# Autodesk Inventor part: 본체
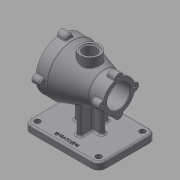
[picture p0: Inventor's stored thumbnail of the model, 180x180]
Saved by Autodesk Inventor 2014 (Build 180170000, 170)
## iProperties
Created: 2020-12
Part Number: 본체
Material: Generic
Document SubType Name: Modeling
Designer: kh
Density: 1 g/cm^3
Appearance: Default
Author: kh
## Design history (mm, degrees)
sketch "스케치1"
  geometry: L1 (-65, 50)-(65, 50); L2 (65, 50)-(65, -50); L3 (65, -50)-(-65, -50); L4 (-65, -50)-(-65, 50); L5 (-65, 50)-(65, -50); L6 (65, 50)-(-65, -50); 1 further point
  constraints: 12 end point, 2 midpoint, 2 parallel, 1 horizontal, 1 perpendicular
  dimensions: "d0" = 130 distance between parallel lines of L2 L4; "d1" = 100 distance between parallel lines of L3 L1
extrude "돌출1" new body sketch "스케치1" distance "d2" = 12; taper "d3" = 0 deg
sketch "스케치2"
  geometry: L1 (50, 82)-(-50, 82); L2 (-50, 82)-(-50, 109.5); L3 (-50, 109.5)-(-25, 109.5); L4 (-25, 109.5)-(30, 126); L5 (30, 126)-(50, 126); L6 (50, 126)-(50, 82); 2 further points
  constraints: 12 end point, 3 parallel, 1 horizontal, 1 midpoint, 1 perpendicular, 1 vertical alignment
  dimensions: "d4" = 82 distance from line of point (0, 0) L1; "d5" = 100 distance between parallel lines of L2 L6; "d6" = 55 diameter of L3 L1; "d7" = 88 diameter of L5 L1; "d8" = 20 distance of L4.end L5.end; "d119" = 25 distance of L2.end L3.end
revolve "회전1" sketch "스케치2" stored, may be unused: angle "d9" = 90 deg
sketch "스케치3"
  geometry: L1 (-24, 74.215)-(24, 74.215); L2 (24, 74.215)-(24, 0); L3 (24, 0)-(-24, 0); L4 (-24, 0)-(-24, 74.215); L5 (-24, 74.215)-(24, 0); L6 (24, 74.215)-(-24, 0); L7 (-65, 0)-(65, 0) reference; 4 further points
  constraints: 12 end point, 5 midpoint, 2 parallel, 1 horizontal, 1 perpendicular, 1 vertical alignment
  dimensions: "d10" = 48 distance between parallel lines of L2 L4
extrude "돌출2" join sketch "스케치3" stored distance "d11" = 8; taper "d12" = 0 deg
sketch "스케치4"
  geometry: L1 (-25, 75.287)-(25, 75.287); L2 (25, 75.287)-(25, 0); L3 (25, 0)-(-25, 0); L4 (-25, 0)-(-25, 75.287); L5 (-25, 75.287)-(25, 0); L6 (25, 75.287)-(-25, 0); 3 further points
  constraints: 12 end point, 4 midpoint, 2 parallel, 1 horizontal, 1 perpendicular, 1 vertical alignment
  dimensions: "d13" = 50 distance between parallel lines of L2 L4
extrude "돌출3" join sketch "스케치4" distance "d14" = 8; taper "d15" = 0 deg
sketch "스케치5"
  geometry: C1 r 7 at (0, 44); 2 further points
  constraints: 2 vertical alignment, 1 centre point, 1 other
  dimensions: "d16" = 7 radius of C1
extrude "돌출4" join sketch "스케치5" distance "d17" = 15; taper "d18" = 0 deg
hole "구멍1" diameter "d21" = 4.134; stored, may be unused: countersink angle "d25" = 90 deg, drill point angle "d27" = 118 deg; dims "d19" = 10, "d20" = 10, "d22" = 9, "d23" = 4, "d24" = 2, "d26" = 11
sketch "스케치6"
  geometry: C1 r 7 at (0, 27.5); 2 further points
  constraints: 2 vertical alignment, 1 centre point, 1 other
  dimensions: "d32" = 7 radius of C1
extrude "돌출5" join sketch "스케치6" distance "d33" = 15; taper "d34" = 0 deg
hole "구멍2" diameter "d37" = 4.134; stored, may be unused: countersink angle "d41" = 90 deg, drill point angle "d43" = 118 deg; dims "d35" = 10, "d36" = 10, "d38" = 9, "d39" = 4, "d40" = 2, "d42" = 11
node "작업 평면1"
sketch "스케치7"
  geometry: C1 r 17 at (0, 0); 1 further point
  constraints: 1 centre point, 1 coincident
  dimensions: "d48" = 34 diameter of C1
extrude "돌출6" join sketch "스케치7" distance "d49" = 32.75; taper "d50" = 0 deg
sketch "스케치8"
  geometry: L1 (50, 82)-(-50, 82); L2 (-50, 82)-(-50, 102); L3 (-50, 102)-(-20, 102); L4 (-20, 102)-(-20, 108); L5 (-20, 108)-(27, 108); L6 (27, 108)-(27, 114); L7 (27, 114)-(50, 114); L8 (50, 114)-(50, 82); L9 (50, 88.978)-(50, 125.443) reference; L10 (50, 89)-(50, 75) reference; L11 (50, 38.557)-(50, 75.022) reference; L12 (-50, 88.943)-(-50, 108.609) reference; L13 (-50, 55.391)-(-50, 75.057) reference; L14 (-50, 79.933)-(-50, 84.067) reference; L15 (-50, 75)-(-50, 89) reference; L16 (50, 133)-(50, 125.443) reference; L17 (50, 38.557)-(35, 38.557) reference; L18 (50, 38.557)-(50, 38.557) reference; L19 (35, 38.557)-(50, 38.557) reference; L20 (35, 38.557)-(35, 38.557) reference; L21 (50, 38.557)-(50, 31) reference; 2 further points
  constraints: 16 end point, 4 parallel, 2 vertical, 1 horizontal, 1 midpoint, 1 perpendicular, 1 point on line
  dimensions: "d51" = 82 distance from line of point (0, 0) L1; "d52" = 64 diameter of L7 L1; "d53" = 52 diameter of L5 L1; "d54" = 40 diameter of L3 L1; "d55" = 100 distance from line of L2 L10.start; "d56" = 23 distance between parallel lines of L6 L8; "d57" = 30 distance between parallel lines of L2 L4
revolve "회전2" sketch "스케치8" stored, may be unused: angle "d58" = 90 deg
hole "구멍3" diameter "d61" = 28; stored, may be unused: countersink angle "d65" = 90 deg, drill point angle "d67" = 0 deg; dims "d59" = 10, "d60" = 10, "d62" = 9, "d63" = 4, "d64" = 2, "d66" = 1
hole "구멍4" diameter "d70" = 22; stored, may be unused: countersink angle "d74" = 90 deg, drill point angle "d76" = 0 deg; dims "d68" = 10, "d69" = 10, "d71" = 9, "d72" = 4, "d73" = 2, "d75" = 33.25
fillet "모깎기1" dims "d77" = 12
hole "구멍5" diameter "d80" = 10; stored, may be unused: countersink angle "d84" = 90 deg, drill point angle "d86" = 0 deg; dims "d78" = 10, "d79" = 10, "d81" = 9, "d82" = 4, "d83" = 2, "d85" = 33.25
fillet "모깎기2" dims "d91" = 3
fillet "모깎기3" dims "d92" = 3
fillet "모깎기4" dims "d93" = 3
fillet "모깎기5" dims "d94" = 3
fillet "모깎기6" dims "d95" = 3
fillet "모깎기7" dims "d96" = 3
fillet "모깎기8" dims "d97" = 3
chamfer "모따기1" distance "d98" = 1; stored, may be unused: second distance "d99" = 2, angle "d100" = 45 deg
fillet "모깎기9" dims "d101" = 3
fillet "모깎기10" dims "d102" = 3
chamfer "모따기2" distance "d103" = 1; stored, may be unused: second distance "d104" = 2, angle "d105" = 45 deg
fillet "모깎기13" dims "d108" = 3
fillet "모깎기14" dims "d109" = 3
fillet "모깎기15" dims "d110" = 1
fillet "모깎기16" dims "d111" = 1
fillet "모깎기18" dims "d113" = 1
sketch "스케치9"
  geometry: L1 (-53, -50)-(53, -50) reference; 2 further points
  constraints: 1 vertical alignment, 1 other
  dimensions: "d114" = 10 distance from line of L1 point (0, -40)
feature "엠보싱1" sketch "스케치9" dims "d115" = 0.5, "d116" = 0
node "솔리드1"
pattern_circular "원형 패턴1" dims angle "d29" = 360 deg
pattern_circular "원형 패턴2" dims angle "d45" = 360 deg
pattern_linear "직사각형 패턴1"
node "투영된 루프1"
other parameters: "d47" = -127
